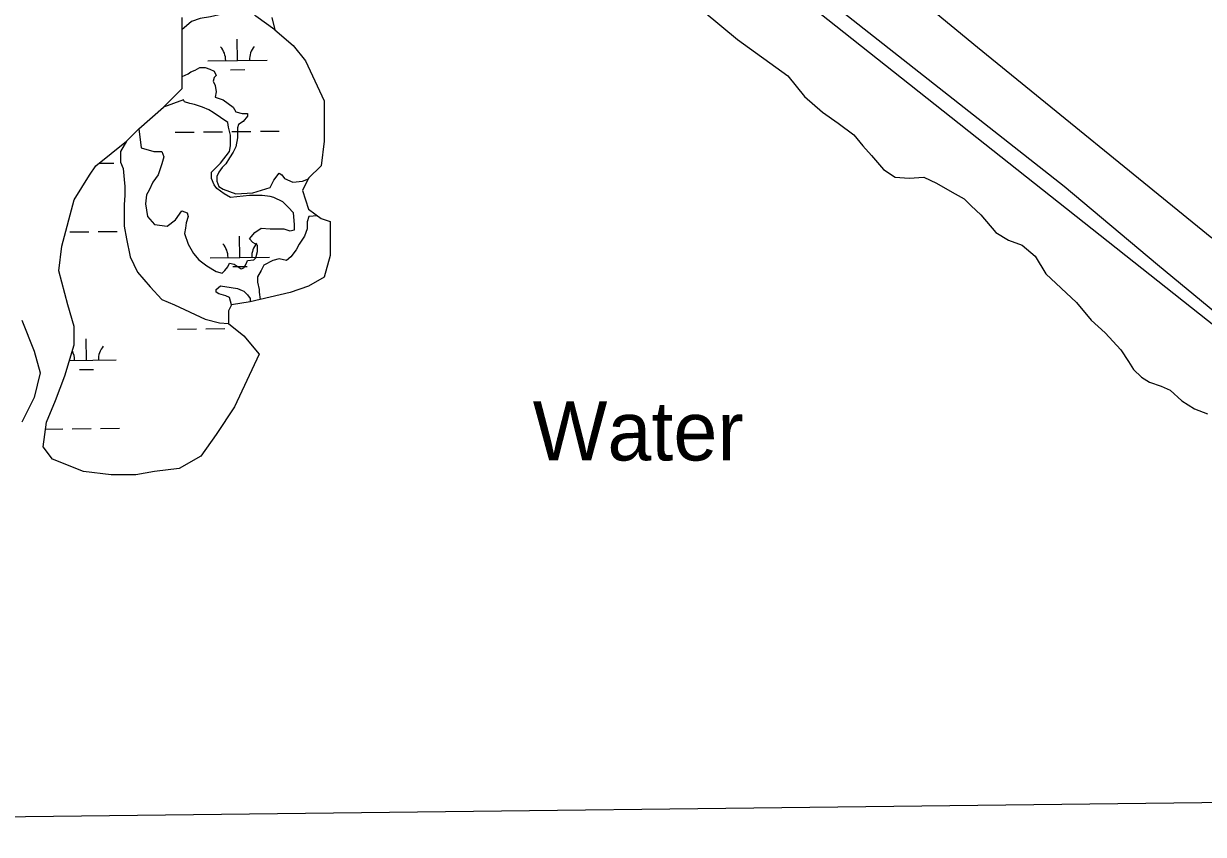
# Model space of a CAD drawing. Extents: x 3694830 to 3732949, y 415201 to 440970.
# Drawn here: x 3701515 to 3703509, y 420616 to 421986 of the extents above; entities that cross this region are included whole.
import ezdxf

# ---------------------------------------------------------------- set-up
doc = ezdxf.new("R2010")
doc.units = 0
for name, color, linetype in [('V-GRID-FRAM', 7, 'Continuous'), ('V-RIVR-IDEN', 7, 'Continuous'), ('V-TOPO-SHOR', 7, 'Continuous'), ('V-UTIL-LINE', 7, 'Continuous'), ('V-WETL-SWMP', 7, 'Continuous')]:
    doc.layers.add(name, color=color, linetype=linetype)

msp = doc.modelspace()

# ---------------------------------------------------------------- linework, layer by layer
at = {"layer": 'V-GRID-FRAM'}
msp.add_lwpolyline([(3698844.7, 438797.5), (3730590.8, 439176.2), (3730815.6, 420995.1), (3699053.6, 420616.3), (3698844.7, 438797.5)], dxfattribs=at)
at = {"layer": 'V-TOPO-SHOR'}
for p, q in [((3701512, 421485), (3701532.8, 421432.8)), ((3701532.8, 421432.8), (3701543.3, 421396.3)), ((3701543.3, 421396.3), (3701532.8, 421354.5)), ((3701532.8, 421354.5), (3701512, 421312.8))]:
    msp.add_line(p, q, dxfattribs=at)
for points in [[(3703523.4, 421623.5), (3703127.6, 421945.9), (3702482.6, 422477.3), (3701973.2, 422891.4), (3701874.3, 422968.4), (3701863.3, 422979.4), (3701863.3, 422994), (3701859.6, 422997.7), (3701844.9, 422997.7), (3701801, 423023.4), (3701540.8, 423235.9), (3701350.2, 423389.8)], [(3701295.2, 423331.2), (3701786.3, 422917.1), (3702262.7, 422528.6), (3702790.4, 422092.5), (3703274.2, 421711.4), (3703431.8, 421579.5), (3703706.6, 421352.3)], [(3701939.7, 421975.6), (3701907.8, 421998.7), (3701899.2, 422007.4), (3701893, 422017.3), (3701883.1, 422028.4), (3701875.7, 422033.4), (3701867, 422032.1), (3701860.9, 422023.5), (3701855.9, 422009.9), (3701851, 422002.5), (3701831.2, 421997.5), (3701813.9, 421995), (3701799.1, 421990.1), (3701786.7, 421979), (3701783.2, 421976.2)], [(3702665.5, 422006.3), (3702722.1, 421959.7), (3702807, 421898.1), (3702835.3, 421863.2), (3702865.3, 421836.5), (3702891.9, 421818.2), (3702918.6, 421798.3), (3702933.6, 421779.9), (3702948.5, 421763.3), (3702968.5, 421740), (3702988.5, 421726.7), (3703011.8, 421725), (3703036.8, 421726.7), (3703058.4, 421716.7), (3703085, 421701.7), (3703105, 421690), (3703116.7, 421678.4), (3703133.3, 421663.4), (3703158.3, 421633.4), (3703179.9, 421620.1), (3703203.2, 421611.8), (3703224.9, 421593.5), (3703243.2, 421563.5), (3703294.8, 421515.2), (3703319.8, 421485.3), (3703343.1, 421463.6), (3703369.7, 421435.3), (3703383, 421415.4), (3703391.4, 421402), (3703404.7, 421388.7), (3703418, 421380.4), (3703438, 421373.7), (3703453, 421367.1), (3703472.9, 421348.8), (3703494.6, 421335.5), (3703516.2, 421327.1)], [(3701783.2, 421897), (3701783.2, 421976.2)], [(3701939.7, 421975.6), (3701971, 421949.5), (3701991.8, 421923.4), (3702023.1, 421855.6), (3702023.1, 421787.7), (3702017.9, 421746), (3701997, 421725.1), (3701996.5, 421724)], [(3701783.2, 421897), (3701793.1, 421901.5), (3701797.7, 421904.6), (3701805.3, 421907.6), (3701813, 421912.2), (3701822.1, 421912.2), (3701829.7, 421909.2), (3701837.3, 421906.1), (3701840.4, 421898.5), (3701837.3, 421895.4), (3701835.8, 421889.3), (3701838.9, 421881.7), (3701840.4, 421871), (3701838.9, 421861.9), (3701852.6, 421857.3), (3701869.4, 421845.1), (3701873.9, 421837.5), (3701884.6, 421834.4), (3701893.8, 421834.4), (3701893.8, 421829.9), (3701886.1, 421820.7), (3701878.5, 421816.1), (3701877, 421810.1), (3701877, 421793.3), (3701873.9, 421778), (3701869.4, 421768.9), (3701863.3, 421759.7), (3701857.2, 421749.1), (3701851.1, 421743), (3701845, 421735.3), (3701841.9, 421727.7), (3701841.9, 421720.1), (3701845, 421710.9), (3701852.6, 421706.4), (3701873.9, 421698.7), (3701902.9, 421700.3), (3701931.9, 421709.4), (3701938, 421721.6), (3701947.1, 421733.8), (3701951.7, 421730.8), (3701956.3, 421724.7), (3701970, 421718.6), (3701986.8, 421720.1), (3701996.5, 421724)], [(3701710.2, 421808.6), (3701713.8, 421776.5), (3701735.2, 421770.4), (3701748.9, 421770.4), (3701752, 421761.3), (3701748.9, 421749.1), (3701742.8, 421730.8), (3701733.7, 421718.6), (3701727.6, 421704.8), (3701723, 421697.2), (3701721.5, 421682), (3701724.5, 421660.6), (3701736.7, 421646.9), (3701758.1, 421643.8), (3701771.8, 421654.5), (3701782.5, 421669.8), (3701791.6, 421666.7), (3701793.1, 421660.6), (3701790.1, 421649.9), (3701788.6, 421640.8), (3701787, 421631.7), (3701793.1, 421613.4), (3701802.3, 421598.1), (3701811.4, 421587.4), (3701825.1, 421576.8), (3701840.4, 421567.6), (3701851.1, 421564.6), (3701855.6, 421569.1), (3701860.2, 421575.2), (3701863.3, 421581.3), (3701870.9, 421579.8), (3701883.1, 421572.2), (3701887.7, 421573.7), (3701892.2, 421581.3), (3701893.8, 421585.9), (3701904.4, 421587.4), (3701907.5, 421590.5), (3701910.5, 421601.2), (3701910.5, 421611.8), (3701902.9, 421616.4), (3701896.8, 421622.5), (3701906, 421633.2), (3701916.6, 421640.8), (3701931.9, 421639.3), (3701954.8, 421639.3), (3701965.4, 421636.2), (3701973.1, 421637.7), (3701973.1, 421646.9), (3701971.5, 421666.7), (3701962.4, 421675.9), (3701953.2, 421685), (3701938, 421692.6), (3701931.9, 421694.2), (3701918.2, 421695.7), (3701896.8, 421695.7), (3701864.8, 421692.6), (3701854.1, 421698.7), (3701841.9, 421707.9), (3701837.3, 421714), (3701832.8, 421724.7), (3701832.8, 421735.3), (3701837.3, 421739.9), (3701848, 421750.6), (3701863.3, 421770.4), (3701864.8, 421779.6), (3701864.8, 421788.7), (3701864.8, 421797.9), (3701861.7, 421811.6), (3701860.2, 421819.2), (3701835.8, 421836), (3701828.2, 421840.5), (3701817.5, 421845.1), (3701803.8, 421849.7), (3701796.2, 421851.2), (3701787, 421854.3), (3701785.5, 421857.3), (3701751.9, 421845.1)], [(3701710.2, 421808.6), (3701751.9, 421845.1)], [(3701861.4, 421479.8), (3701887.5, 421458.9), (3701913.6, 421427.6), (3701871.9, 421338.9), (3701840.6, 421291.9), (3701814.5, 421255.4), (3701778, 421234.5), (3701736.3, 421229.3), (3701705, 421224.1), (3701663.2, 421224.1), (3701616.3, 421229.3), (3701564.1, 421250.2), (3701548.5, 421271), (3701553.7, 421312.8), (3701569.3, 421349.3), (3701585, 421391.1), (3701600.6, 421443.3), (3701600.6, 421474.6), (3701590.2, 421511.1), (3701574.6, 421568.5), (3701579.8, 421610.3), (3701600.6, 421688.6), (3701626.7, 421730.3), (3701637.2, 421746), (3701689.3, 421787.7)], [(3701689.3, 421787.7), (3701678.8, 421770.4), (3701678.8, 421752.1), (3701683.3, 421741.4), (3701684.9, 421723.1), (3701686.4, 421710.9), (3701686.4, 421695.7), (3701684.9, 421680.4), (3701684.9, 421663.7), (3701684.9, 421643.8), (3701689.4, 421622.5), (3701695.5, 421592), (3701707.7, 421566.1), (3701729.1, 421541.7), (3701748.9, 421520.3), (3701770.3, 421511.2), (3701822.1, 421486.8), (3701846.5, 421480.7), (3701861.4, 421479.8)], [(3702011.9, 421661.7), (3701997.4, 421660.6), (3701994.4, 421651.5), (3701994.4, 421639.3), (3701989.8, 421627.1), (3701980.7, 421613.4), (3701976.1, 421604.2), (3701967, 421592), (3701959.3, 421585.9), (3701947.1, 421589), (3701936.5, 421585.9), (3701921.2, 421578.3), (3701916.6, 421569.1), (3701910.5, 421558.5), (3701910.5, 421549.3), (3701913.6, 421537.1), (3701913.6, 421532.5), (3701915.3, 421520.3)], [(3702011.9, 421661.7), (3702017.9, 421657.2), (3702033.6, 421652), (3702033.6, 421594.6), (3702023.1, 421558.1), (3701997, 421542.4), (3701965.8, 421532), (3701915.3, 421520.3)], [(3701866.7, 421511.1), (3701863.3, 421523.4), (3701857.2, 421526.4), (3701845, 421529.5), (3701840.4, 421532.5), (3701840.4, 421537.1), (3701848, 421543.2), (3701866.3, 421540.2), (3701877, 421538.6), (3701884.6, 421535.6), (3701887.7, 421534.1), (3701893.8, 421528), (3701898.3, 421521.9), (3701897.9, 421516.3)], [(3701897.9, 421516.3), (3701866.7, 421511.1)]]:
    msp.add_lwpolyline(points, dxfattribs=at)
at = {"layer": 'V-UTIL-LINE'}
msp.add_lwpolyline([(3698993.6, 425837.3), (3700191.7, 424338.2), (3700626.5, 423773.3), (3703781.5, 421275.3), (3704475, 420680.9)], dxfattribs=at)
at = {"layer": 'V-WETL-SWMP'}
for p, q in [((3701876.8, 421924), (3701876.4, 421960)), ((3701826.8, 421923.4), (3701926.8, 421924.6)), ((3701865, 421908.4), (3701889, 421908.7)), ((3701771.4, 421802.6), (3701803.4, 421803)), ((3701819.4, 421803.2), (3701851.4, 421803.6)), ((3701867.4, 421803.8), (3701899.4, 421804.2)), ((3701915.4, 421804.3), (3701947.4, 421804.7)), ((3701642.6, 421750.3), (3701667.5, 421750.6)), ((3701593.4, 421634.3), (3701625.4, 421634.7)), ((3701641.4, 421634.9), (3701673.4, 421635.3)), ((3701880.8, 421591.3), (3701880.4, 421627.3)), ((3701830.8, 421590.7), (3701930.8, 421591.9)), ((3701869, 421575.7), (3701893, 421576)), ((3701512, 421485), (3701532.8, 421432.8)), ((3701621.4, 421417.4), (3701621, 421453.4)), ((3701775.4, 421470), (3701807.4, 421470.4)), ((3701823.4, 421470.5), (3701855.4, 421470.9)), ((3701871.4, 421471.1), (3701872.3, 421471.1)), ((3701532.8, 421432.8), (3701543.3, 421396.3)), ((3701592.8, 421417.1), (3701671.4, 421418)), ((3701543.3, 421396.3), (3701532.8, 421354.5)), ((3701609.6, 421401.8), (3701633.6, 421402.1)), ((3701532.8, 421354.5), (3701512, 421312.8)), ((3701552.2, 421301.1), (3701581.4, 421301.5)), ((3701597.4, 421301.7), (3701629.4, 421302)), ((3701645.4, 421302.2), (3701677.4, 421302.6))]:
    msp.add_line(p, q, dxfattribs=at)
msp.add_lwpolyline([(3701934.5, 421996.5), (3701939.7, 421975.6), (3701971, 421949.5), (3701991.8, 421923.4), (3702023.1, 421855.6), (3702023.1, 421787.7), (3702017.9, 421746), (3701997, 421725.1), (3701986.6, 421704.2), (3701997, 421672.9), (3702017.9, 421657.2), (3702033.6, 421652), (3702033.6, 421594.6), (3702023.1, 421558.1), (3701997, 421542.4), (3701965.8, 421532), (3701897.9, 421516.3), (3701866.7, 421511.1), (3701861.4, 421500.7), (3701861.4, 421479.8), (3701887.5, 421458.9), (3701913.6, 421427.6), (3701871.9, 421338.9), (3701840.6, 421291.9), (3701814.5, 421255.4), (3701778, 421234.5), (3701736.3, 421229.3), (3701705, 421224.1), (3701663.2, 421224.1), (3701616.3, 421229.3), (3701564.1, 421250.2), (3701548.5, 421271), (3701553.7, 421312.8), (3701569.3, 421349.3), (3701585, 421391.1), (3701600.6, 421443.3), (3701600.6, 421474.6), (3701590.2, 421511.1), (3701574.6, 421568.5), (3701579.8, 421610.3), (3701600.6, 421688.6), (3701626.7, 421730.3), (3701637.2, 421746), (3701689.3, 421787.7), (3701710.2, 421808.6), (3701751.9, 421845.1), (3701783.2, 421876.4), (3701783.2, 421996.5)], dxfattribs=at)
for centre, start, end in [((3701821.6, 421923.8), 359.9115, 41.4552), ((3701932.1, 421925.1), 139.9115, 181.4552), ((3701825.6, 421591.1), 359.9115, 41.4552), ((3701936, 421592.4), 139.9115, 181.4552), ((3701566.2, 421417.2), 359.9115, 26.8937), ((3701676.7, 421418.5), 139.9115, 181.4552)]:
    msp.add_arc(centre, 35.2, start, end, dxfattribs=at)

# ---------------------------------------------------------------- texts
at = {"layer": 'V-RIVR-IDEN'}
msp.add_text('Water', height=100, dxfattribs=at).set_placement((3702375.8, 421248.1))

doc.saveas('drawing.dxf')
